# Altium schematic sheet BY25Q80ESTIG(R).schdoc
size 127 x 101 mm
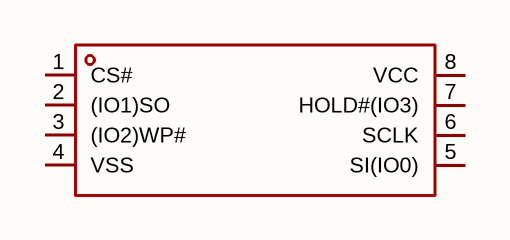
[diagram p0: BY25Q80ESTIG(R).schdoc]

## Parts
U?  by25q80estig(r)  [SOP-8_L4.9-W3.9-P1.27-LS6.0-BL]  (value not drawn)

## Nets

Not connected (* = marked no-connect by the designer): U? 1(CS#) 2((IO1)SO) 3((IO2)WP#) 4(VSS) 5(SI(IO0)) 6(SCLK) 7(HOLD#(IO3)) 8(VCC)

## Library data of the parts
U? = by25q80estig(r): 接口类型:SPI;存储容量:8Mbit;时钟频率(fc):120MHz;; Manufacturer: BOYAMICRO(博雅); AddInBom: yes; ModelId: 75c24a7891ee4dd6bdac16a7163ff87e; ModelName: SOP-8_L4.9-W3.9-P1.27-LS6.0-BL-1; ModelTransform: 192.913,236.22,0,0,0,0,-0.393,2.749,0; Interface: SPI; Memory Size: 8Mbit; Clock Frequency: 120MHz; Voltage - Supply: 2.7V~3.6V; Standby Supply Current: 5uA; Program / Erase Cycles: 100000次; Page Programming Time (Tpp): 400us; Block Erase Time(tBE): 150ms@64KB; Data Retention - TDR (Year): 20年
